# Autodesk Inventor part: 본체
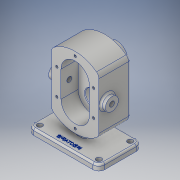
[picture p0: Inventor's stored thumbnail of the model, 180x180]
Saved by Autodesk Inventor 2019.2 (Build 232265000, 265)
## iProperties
Created: 2019-03
Part Number: 본체
Material: 알루미늄 6061
Document SubType Name: Modeling
Designer: User
Density: 2.7 g/cm^3
Appearance: 알루미늄 - 평지
Mass: 1187.18 g
Surface Area: 719.275 cm^2
Volume: 439.697 cm^3
Author: User
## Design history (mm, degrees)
sketch "스케치1"
  geometry: L1 (-40, 122.721)-(-40, 33.279); L2 (40, 122.721)-(40, 33.279); L3 (0, 165.6)-(0, -27.6) reference; L4 (-56, 0)-(56, 0) reference; A1 r 60 centre (0, 78) between (-40, 33.279) and (40, 33.279); A2 r 60 centre (0, 78) between (40, 122.721) and (-40, 122.721); 1 further point
  constraints: 4 end point, 4 point on circle, 2 centre point, 2 vertical, 1 point on line
  dimensions: "d2" = 80 distance between parallel lines of L2 L1; "d3" = 40 distance between parallel lines of L2 L3; "d6" = 60 radius of A2; "d7" = 60 radius of A1; "d8" = 78 distance from line of L4 A1.centre
extrude "돌출1" new body sketch "스케치1" distance "d9" = 53; taper "d10" = 0 deg
sketch "스케치2"
  geometry: L1 (-60, 73)-(60, 73); L2 (60, 73)-(60, 0); L3 (60, 0)-(-60, 0); L4 (-60, 0)-(-60, 73); L5 (0, -14.6)-(0, 87.6) reference; L6 (-84, 0)-(84, 0) reference; 1 further point
  constraints: 8 end point, 2 parallel, 1 horizontal, 1 perpendicular
  dimensions: "d11" = 73 distance between parallel lines of L3 L1; "d12" = 120 distance between parallel lines of L4 L2; "d13" = 60 distance between parallel lines of L2 L5; "d14" = 0 distance between parallel lines of L6 L3
extrude "돌출2" join sketch "스케치2" distance "d15" = 10; taper "d16" = 0 deg
sketch "스케치3"
  geometry: L1 (6, -43)-(-6, -43); L2 (-6, -43)-(-6, 0); L3 (-6, 0)-(6, 0); L4 (6, 0)-(6, -43); L5 (84, 0)-(-84, 0) reference; L6 (0, 14.6)-(0, -87.6) reference; 1 further point
  constraints: 8 end point, 2 parallel, 1 horizontal, 1 perpendicular
  dimensions: "d17" = 12 distance of L1.start L1.end; "d18" = 43 distance of L3.end L1.start; "d19" = 0 distance between parallel lines of L5 L3; "d20" = 6 distance between parallel lines of L6 L2
extrude "돌출3" join sketch "스케치3" distance "d21" = 12; taper "d22" = 0 deg
sketch "스케치4"
  geometry: L1 (-53, 0)-(-53, 89.443) reference; L2 (-87.6, -33.279)-(14.6, -33.279) reference; C1 r 11 at (-39, 44.721); 1 further point
  constraints: 1 centre point
  dimensions: "d23" = 22 diameter of C1; "d24" = 14 distance from line of L1 C1.centre; "d25" = 78 distance from line of L2 C1.centre
extrude "돌출4" join sketch "스케치4" distance "d26" = 8; taper "d27" = 0 deg
sketch "스케치5"
  geometry: L1 (60, 0)-(-60, 0) reference; L2 (0, -27.6)-(0, 165.6) reference; C1 r 19 at (0, 100); 1 further point
  constraints: 1 centre point, 1 point on line
  dimensions: "d28" = 38 diameter of C1; "d29" = 100 distance from line of L1 C1.centre
extrude "돌출5" join sketch "스케치5" distance "d30" = 17; taper "d31" = 0 deg
sketch "스케치6"
  geometry: L1 (0, 32)-(0, 124); L2 (-24, 56)-(-24, 100); L3 (24, 100)-(24, 56); L4 (0, 165.6)-(0, -27.6) reference; L5 (-84, 0)-(84, 0) reference; A1 r 24 centre (0, 56) between (-24, 56) and (24, 56); A2 r 24 centre (0, 100) between (24, 100) and (-24, 100); 2 further points
  constraints: 8 end point, 6 point on circle, 4 tangent, 3 point on line, 2 centre point, 1 midpoint, 1 parallel, 1 vertical
  dimensions: "d32" = 24 distance between parallel lines of L1 L3; "d33" = 44 distance of A1.centre A2.centre; "d34" = 78 distance from line of L5 point (0, 78)
extrude "돌출6" cut sketch "스케치6" distance "d35" = 29; taper "d36" = 0 deg
sketch "스케치7"
  geometry: C1 r 19 at (0, 0) reference; 2 further points
  constraints: 1 coincident
hole "구멍1" sketch "스케치7" at (0, 0) diameter "d37" = 17; stored, may be unused: countersink angle "d41" = 82 deg, drill point angle "d43" = 0 deg; dims "d38" = 8, "d39" = 28, "d40" = 7.3, "d42" = 50
sketch "스케치8"
  geometry: C1 r 8.5 at (0, 100) reference; 2 further points
  constraints: 1 coincident
hole "구멍2" sketch "스케치8" at (0, 100) diameter "d44" = 25; stored, may be unused: countersink angle "d48" = 82 deg, drill point angle "d50" = 0 deg; dims "d45" = 8, "d46" = 28, "d47" = 7.3, "d49" = 15
sketch "스케치9"
  geometry: A1 r 24 centre (0, 56) between (-24, 56) and (24, 56) reference; 2 further points
  constraints: 1 coincident
hole "구멍3" sketch "스케치9" at (0, 56) diameter "d51" = 25; stored, may be unused: countersink angle "d55" = 82 deg, drill point angle "d57" = 0 deg; dims "d52" = 8, "d53" = 28, "d54" = 7.3, "d56" = 15
sketch "스케치10"
  geometry: C1 r 11 at (0, 0) reference; 2 further points
  constraints: 1 coincident
hole "구멍4" sketch "스케치10" at (0, 0) diameter "d58" = 8.376; stored, may be unused: countersink angle "d62" = 82 deg, drill point angle "d64" = 0 deg; dims "d59" = 40, "d60" = 28, "d61" = 7.3, "d63" = 40
sketch "스케치11"
  geometry: C1 r 11 at (0, 0) reference; 2 further points
  constraints: 1 coincident
hole "구멍5" sketch "스케치11" at (0, 0) diameter "d65" = 8.376; stored, may be unused: countersink angle "d69" = 82 deg, drill point angle "d71" = 0 deg; dims "d66" = 40, "d67" = 28, "d68" = 7.3, "d70" = 40
sketch "스케치12"
  geometry: L1 (0, 56)-(0, 100); L2 (31, 56)-(31, 100); L3 (-31, 100)-(-31, 56); L4 (0, 165.6)-(0, -27.6) reference; C1 r 8.5 at (0, 100) reference; A1 r 31 centre (0, 56) between (-31, 56) and (31, 56); A2 r 31 centre (0, 100) between (31, 100) and (-31, 100); 8 further points
  constraints: 9 point on circle, 8 end point, 4 tangent, 3 point on line, 2 centre point, 1 midpoint, 1 parallel, 1 vertical
  dimensions: "d79" = 31 radius of A2; "d80" = 44 distance of L1.start L1.end; "d81" = 44 distance of point (31, 56) point (31, 100); "d82" = 44 distance of point (-31, 56) point (-31, 100); "d83" = 22 vertical distance of point (0, 78) point (-31, 100); "d84" = 22 vertical distance of point (0, 78) point (31, 100)
hole "구멍6" sketch "스케치12" at (31, 100), (0, 131), (-31, 100), (-31, 56), (31, 56), (0, 25) diameter "d72" = 4.134; stored, may be unused: countersink angle "d76" = 82 deg, drill point angle "d78" = 118 deg; dims "d73" = 10, "d74" = 28, "d75" = 7.3, "d77" = 12
fillet "모깎기1" dims "d85" = 10
fillet "모깎기3" dims "d94" = 3
fillet "모깎기4" dims "d95" = 10
fillet "모깎기7" dims "d98" = 3
fillet "모깎기10" dims "d101" = 3
fillet "모깎기11" dims "d102" = 3
fillet "모깎기12" dims "d103" = 3
sketch "스케치14"
  geometry: A1 r 7 centre (50, -63) between (50, -70) and (57, -63) reference; A2 r 7 centre (-50, -63) between (-57, -63) and (-50, -70) reference; A3 r 7 centre (50, -10) between (57, -10) and (50, -3) reference; A4 r 7 centre (-50, -10) between (-50, -3) and (-57, -10) reference; 5 further points
  constraints: 4 coincident
hole "구멍8" sketch "스케치14" at (50, -63), (-50, -63), (50, -10), (-50, -10) diameter "d104" = 9; stored, may be unused: countersink angle "d108" = 82 deg, drill point angle "d110" = 0 deg; dims "d105" = 10, "d106" = 28, "d107" = 7.3, "d109" = 12
chamfer "모따기1" distance "d111" = 1; stored, may be unused: second distance "d112" = 2, angle "d113" = 45 deg
chamfer "모따기4" distance "d120" = 0.7; stored, may be unused: second distance "d121" = 2, angle "d122" = 30 deg
fillet "모깎기13" dims "d123" = 0.5
sketch "스케치17"
  geometry: L1 (-50, -73)-(50, -73) reference; L2 (-60, -10)-(-60, -63) reference; 2 further points
  constraints: 1 other
  dimensions: "d124" = 10 distance from line of L1 point (0, -63); "d125" = 60 distance from line of L2 point (0, -63)
feature "엠보싱1" sketch "스케치17" dims "d2" = 80, "d3" = 40, "d6" = 60, "d7" = 60, "d8" = 78, "d17" = 12, "d18" = 43, "d19" = 0, "d20" = 6, "d126" = 0.5, "d127" = 0
fillet "모깎기14" dims "d128" = 3
node "솔리드1"
mirror "미러1"
